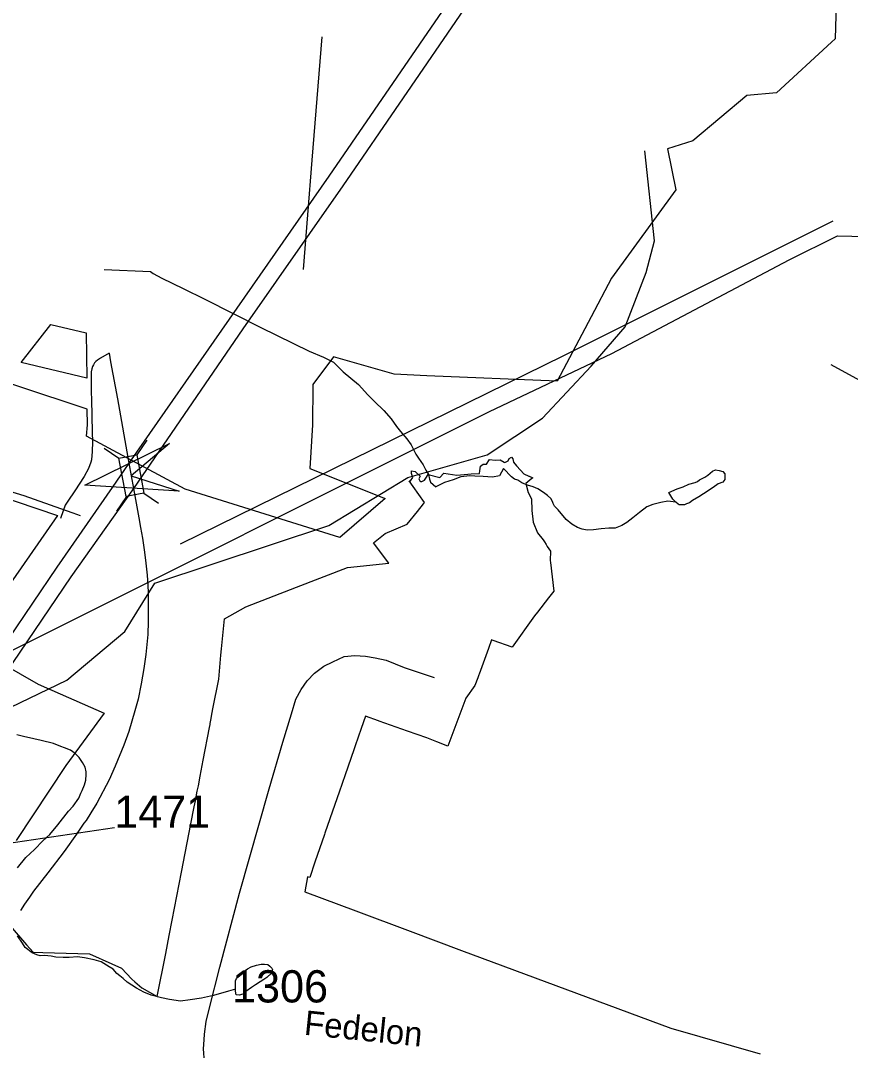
# Model space of a CAD drawing. Extents: x 2260773 to 2342389, y 552869 to 618546.
# Drawn here: x 2298424 to 2301642, y 607573 to 611569 of the extents above; entities that cross this region are included whole.
import ezdxf

# ---------------------------------------------------------------- set-up
doc = ezdxf.new("R2010")
doc.units = 0
for name, color, linetype in [('Exist Boundary Political City Limit New', 7, 'Continuous'), ('Exist Hydrographic Creek Single Shore', 7, 'Continuous'), ('Exist Hydrographic Misc Water Feature', 7, 'Continuous'), ('Exist Road Non-System Type 51', 7, 'Continuous'), ('Exist Road Primary Interstate Divided Center Attributed', 7, 'Continuous'), ('Exist Road Secondary Structure Standard Bridge Attributed CELL', 7, 'Continuous'), ('Exist Road Secondary Structure Standard Bridge CELL', 7, 'Continuous'), ('Exist Road Secondary Type 51 Attributed', 7, 'Continuous'), ('Exist Road Secondary Type 51 Label', 7, 'Continuous'), ('Exist Road Secondary Type 51 Number Label', 7, 'Continuous'), ('Exist Utilities Electrical Transmission Line', 7, 'Continuous'), ('Map Preparation Boundary City Limit Buffer Line', 7, 'Continuous')]:
    doc.layers.add(name, color=color, linetype=linetype)

msp = doc.modelspace()

# ---------------------------------------------------------------- linework, layer by layer
at = {"layer": 'Exist Boundary Political City Limit New'}
for points in [[(2301595.8, 611955.4), (2301583.2, 611498.7), (2301568.8, 611485.4), (2301355, 611288.4), (2301239.8, 611278.1), (2301030.8, 611103.3), (2300932.2, 611071.2), (2300965.2, 610913), (2300715, 610569.1), (2300636.5, 610420), (2300504.5, 610169.6), (2300000, 610191.3), (2299872.8, 610197.1), (2299637, 610264.2), (2299557.5, 610157), (2299557, 610156.4), (2299557, 610153.1), (2299555.8, 610000), (2299545.5, 609830.8), (2299838.2, 609714.4), (2299662.5, 609563.6), (2299062.8, 609750.7), (2298680.2, 609957.1), (2298683.8, 610000)], [(2298542, 610390.1), (2298678, 610357.3), (2298681.5, 610181.9), (2298427, 610242.6), (2298542, 610390.1)], [(2298683.8, 610000), (2298683, 610060.9), (2298635.8, 610076.6), (2297935.5, 610308.8)], [(2298319.2, 608129.9), (2298446.8, 607983.2), (2298473, 607953.8), (2298509.8, 607952.9), (2298691, 607948.4), (2298777.5, 607909.4), (2298815, 607892.5), (2298855.8, 607850), (2298867.5, 607839.4), (2298894, 607815.5), (2298954.2, 607782.6), (2298986.8, 607949.6), (2299000, 608018.4), (2299011.5, 608078.2), (2299048, 608264.7), (2299084.8, 608452.2), (2299097.8, 608518.5), (2299102.2, 608541.6), (2299109.5, 608578.9), (2299113.5, 608599.8), (2299120.5, 608636.8), (2299132.5, 608699.1), (2299156.8, 608825.7), (2299159.2, 608837.9), (2299159.8, 608841.7), (2299162, 608854.1), (2299167, 608883.8), (2299169.5, 608897.9), (2299192.5, 609013.3), (2299201, 609106.6), (2299203.2, 609131.4), (2299214.5, 609247.9), (2299297.5, 609294.4), (2299494.5, 609370.5), (2299691.8, 609446.5), (2299851.8, 609463.5), (2299793.2, 609542.6), (2299838, 609578.6), (2299923, 609615.1), (2299963.2, 609664.7), (2299987, 609694.1), (2299990.8, 609698.7), (2299946, 609761.8), (2299930.8, 609783), (2299936.5, 609783.9), (2299945, 609796.4), (2299939.5, 609811.6), (2299939.5, 609821.7), (2299954.8, 609819), (2299973.2, 609802), (2299968.2, 609790.6), (2299971.8, 609782.8), (2299976.2, 609781.3), (2299979.5, 609780.2), (2299990.5, 609785.6), (2299995.2, 609793.1), (2300005, 609808.2), (2300049.8, 609796.4), (2300065.8, 609812.8), (2300115.5, 609804.7), (2300158.5, 609809.4), (2300171.2, 609809.9), (2300203.5, 609811.2), (2300205, 609822.1), (2300207.2, 609840), (2300218, 609848.2), (2300230.5, 609847.6), (2300242.8, 609866.1), (2300264.2, 609863.6), (2300284.2, 609864.7), (2300300, 609856.2), (2300302.5, 609854.9), (2300314.5, 609861.4), (2300318.2, 609870.2), (2300327.2, 609874.7), (2300332.8, 609868.6), (2300335.8, 609856.2), (2300347.8, 609841.1), (2300348.5, 609840.2)], [(2300348.5, 609840.2), (2300375.8, 609810.8), (2300395, 609802), (2300395.8, 609801.6), (2300410.2, 609795.2), (2300407, 609792.4), (2300383.5, 609773.2), (2300392.2, 609738.4), (2300405, 609712.9), (2300406.5, 609668.4), (2300411.5, 609622.7), (2300428.8, 609581.6), (2300450.2, 609553.7), (2300455.8, 609546.5), (2300462, 609535.8), (2300466.5, 609528.8), (2300479, 609510), (2300478, 609473.5), (2300479, 609466.6), (2300491.5, 609354.9), (2300471.2, 609329.1), (2300428, 609273.9), (2300416.5, 609259.2), (2300330.2, 609138.2), (2300257.2, 609164.2), (2300250.5, 609166.7), (2300238, 609132.6), (2300201.8, 609033.1), (2300200.8, 609030.2), (2300196.8, 609019.1), (2300185.8, 608988.9), (2300150.8, 608939.6), (2300093.2, 608785.1), (2300081.5, 608753.8), (2300038.2, 608770.5), (2300000, 608785.4), (2299924.2, 608812.3), (2299814.5, 608851.2), (2299811.8, 608852.2), (2299761.8, 608869.9), (2299745.2, 608822.2), (2299722.2, 608755.4), (2299716.8, 608739.6), (2299683, 608642.1), (2299659.8, 608575.2), (2299643.2, 608527.7), (2299604.5, 608415.8), (2299602.8, 608410.7), (2299565.8, 608303.5), (2299545.2, 608244.4), (2299536.8, 608246.7), (2299525.8, 608188), (2299724.2, 608114.2), (2299934.8, 608036.1), (2300134.2, 607960.1), (2300945.8, 607659.8), (2301291.8, 607559.1)], [(2298325.2, 609730.6), (2298567, 609649.4), (2298328.2, 609305.6)], [(2298220.8, 609150), (2298492, 608994.4), (2298747.8, 608881.1), (2298599.5, 608678.1), (2298407, 608388.1)]]:
    msp.add_lwpolyline(points, dxfattribs=at)
at = {"layer": 'Exist Hydrographic Creek Single Shore'}
msp.add_lwpolyline([(2298012.3, 608776.9), (2298210.8, 608879.9), (2298386.5, 608905), (2298603.8, 609010.2), (2298828.3, 609199), (2298945.2, 609385.7)], dxfattribs=at)
at = {"layer": 'Exist Hydrographic Misc Water Feature'}
for points in [[(2299521.5, 610603.9), (2299554.9, 611027.9), (2299593.9, 611506.3)], [(2298945.2, 609385.7), (2299618.9, 609609.6), (2299925.9, 609795.9), (2300232.9, 609883.8), (2300447.9, 610027), (2300637, 610228.3), (2300769.1, 610381.3), (2300850.1, 610591.3), (2300882, 610714.1), (2300844.9, 611063.6)], [(2298747.9, 610603.6), (2298928.1, 610595.6), (2298937.7, 610587.6), (2298972.2, 610570.3), (2299054.2, 610529.1), (2299138.7, 610488), (2299356, 610378.2), (2299543.1, 610286.4), (2299599, 610263), (2299637, 610243.5), (2299675.7, 610206), (2299734.4, 610156.6), (2299770.7, 610116.7), (2299796.5, 610091.3), (2299833.2, 610055.8), (2299861.5, 610024), (2299881.6, 609994.1), (2299897.8, 609974.3), (2299922, 609946.6), (2299938.4, 609922.7), (2299956.9, 609887.1), (2299966.9, 609871), (2299985.1, 609845.5), (2299995.4, 609825.3), (2300005.7, 609807.6), (2300010, 609789.9), (2300013.9, 609777.9), (2300034.2, 609759.8)], [(2300297.2, 609830.9), (2300281.4, 609802.5), (2300254, 609798.1), (2300217.7, 609799.9), (2300185.7, 609801.5), (2300166, 609803.3), (2300131.8, 609799.1), (2300102, 609786.6), (2300068, 609776.2), (2300040.1, 609762.2), (2300034.2, 609759.8)], [(2300964.5, 609700.1), (2300933.9, 609703.9), (2300906.4, 609699.5), (2300876.5, 609691), (2300852.7, 609682.8), (2300824.8, 609660.7), (2300798.8, 609640.2), (2300775, 609621.9), (2300755.5, 609609.8), (2300729.7, 609599.6), (2300705.3, 609599.2), (2300675.8, 609597.1), (2300645.6, 609592.8), (2300621.8, 609592.3), (2300601.5, 609596.2), (2300583.9, 609602.1), (2300561.3, 609615.6), (2300539.4, 609633.5), (2300509.1, 609670.9), (2300494.7, 609684.8), (2300488.8, 609695), (2300486.7, 609702.7), (2300480.6, 609714.9), (2300468, 609726.6), (2300452.3, 609738.3), (2300429.9, 609752.2), (2300411.7, 609760.2), (2300390.1, 609765.9), (2300368, 609775.7), (2300351.8, 609785.5), (2300339.7, 609789.3), (2300327.6, 609799.2), (2300297.2, 609830.9)], [(2300964.5, 609700.1), (2300954, 609711.8), (2300938, 609737.7), (2300969.6, 609752), (2300994, 609760.1), (2301015.7, 609770.6), (2301039.5, 609776.8), (2301049.2, 609781), (2301057.2, 609787.1), (2301077.5, 609797), (2301088.9, 609805.4), (2301107, 609821.4), (2301118.7, 609825.7), (2301132.8, 609823.6), (2301147.2, 609819.8), (2301154.8, 609810.1), (2301155, 609795.9), (2301155, 609788.2), (2301147.4, 609778), (2301129.7, 609771.7), (2301109.7, 609757.7), (2301071.9, 609733), (2301053.7, 609721.1), (2301030.1, 609706.8), (2301018.2, 609698.5), (2301006.3, 609694.6), (2300998.5, 609690.5), (2300978.4, 609690.3), (2300974.5, 609692.1), (2300964.5, 609700.1)], [(2298412.8, 608281.3), (2298444.2, 608321.6), (2298478.2, 608352.2), (2298510.2, 608386.3), (2298537.7, 608410.5), (2298569.1, 608448.8), (2298610.5, 608501.3), (2298627.9, 608521.4), (2298649.8, 608551.8), (2298657.4, 608571.7), (2298663.4, 608581.8), (2298671.4, 608604.1), (2298676.9, 608621.9), (2298679, 608644), (2298678.8, 608654), (2298674.7, 608671.7), (2298664.4, 608689.9), (2298651.9, 608709.6), (2298635.9, 608725.4), (2298617.9, 608737.5), (2298594.1, 608747.1), (2298580.1, 608752.9), (2298551.4, 608764.5), (2298503.6, 608776.2), (2298475.8, 608781.6), (2298435.2, 608791.3), (2298409.5, 608797.2)], [(2299257.6, 607810.6), (2299229.9, 607802.6), (2299171.9, 607785.8), (2299126, 607775.2), (2299081.9, 607768.9), (2299044.2, 607764.4), (2299002.1, 607770), (2298970.3, 607777.6), (2298929.9, 607787.3), (2298902.1, 607798.8), (2298873.6, 607814.5), (2298855.7, 607826.5), (2298837.7, 607838.1), (2298821.7, 607851.9), (2298809.2, 607861.9), (2298797.3, 607871.8), (2298782.9, 607887.8), (2298767.1, 607897.4), (2298736.4, 607917), (2298708.9, 607924.9), (2298672.6, 607932.3), (2298644.7, 607936.1), (2298612.5, 607933.7), (2298588.7, 607933.6), (2298560.4, 607935), (2298542.4, 607939), (2298516.8, 607940.8), (2298500.6, 607940.4), (2298486.8, 607944.5), (2298468.6, 607952.1), (2298442.5, 607971.8), (2298431.9, 607989.7), (2298411.8, 608017.5)], [(2299257.6, 607810.6), (2299257.2, 607818.8), (2299257.4, 607832.5), (2299257.4, 607842.7), (2299261.1, 607852.6), (2299271, 607862.9), (2299281.2, 607872.7), (2299304.6, 607889.1), (2299318.7, 607897.5), (2299338.4, 607903.5), (2299356.7, 607907.6), (2299370.2, 607908), (2299382.3, 607906.2), (2299390.7, 607900.1), (2299398.7, 607892.3), (2299400.7, 607886.4), (2299397.1, 607872.3), (2299379, 607856), (2299367.1, 607848), (2299353, 607839.6), (2299335.7, 607827.6), (2299319.5, 607817.5), (2299297.6, 607801.3), (2299285.7, 607790.9), (2299272, 607786.9), (2299259.9, 607788.7), (2299257.6, 607802.9), (2299257.6, 607810.6)]]:
    msp.add_lwpolyline(points, dxfattribs=at)
at = {"layer": 'Exist Road Non-System Type 51'}
for p, q in [((2298627.5, 609657.9), (2298580.5, 609674.6)), ((2298656.3, 609647.6), (2298627.5, 609657.9))]:
    msp.add_line(p, q, dxfattribs=at)
for points in [[(2302669.5, 609785.8), (2302626.9, 609800), (2302263.5, 609920.8), (2301997.8, 610015.3), (2301874.8, 610070.3), (2301782.6, 610123), (2301664, 610180.1), (2301567.3, 610232.9)], [(2298580.5, 609674.6), (2298438.2, 609725.3), (2298348.8, 609751.6), (2298326.9, 609773.6), (2298279.4, 609821.1)], [(2299136.1, 607614), (2299137.4, 607635.5), (2299144, 607684.9), (2299157.2, 607737.7), (2299196.7, 607895.9), (2299272.5, 608182.7), (2299387.8, 608588.1), (2299440.5, 608769.4), (2299474.5, 608879.2), (2299492.1, 608936.4), (2299511.8, 608973.7), (2299536, 609006.7), (2299564.5, 609037.5), (2299599.7, 609063.8), (2299634.8, 609081.4), (2299678.7, 609101.2), (2299720.5, 609105.6), (2299762.2, 609103.4), (2299799.5, 609096.8), (2299841.2, 609088), (2299911.5, 609059.4), (2300027.9, 609019.9)], [(2299137.4, 607527.2), (2299134.1, 607579.5), (2299136.1, 607614)]]:
    msp.add_lwpolyline(points, dxfattribs=at)
at = {"layer": 'Exist Road Primary Interstate Divided Center Attributed'}
for points in [[(2301053.9, 613030.6), (2300322.2, 611991.3), (2299619.5, 610965.1), (2299232.7, 610410.4), (2298844.5, 609852.1)], [(2301111.8, 612998.5), (2300376.1, 611953.9), (2299673.5, 610927.8), (2299286.6, 610372.9), (2298862.1, 609753.4)], [(2298844.5, 609852.1), (2298779.6, 609757.5), (2298564.9, 609447.7), (2298280.6, 609029.8), (2298078.5, 608714.6), (2297910.7, 608420), (2297811.4, 608214.4), (2297736.1, 608043.2), (2297575.1, 607625.2), (2297438.1, 607145.6), (2297328.5, 606669.4), (2297208.7, 606052.8), (2297112.8, 605669.1), (2297040.9, 605439.5), (2296893.6, 605018.2), (2296605.9, 604305.6), (2296386.7, 603730), (2296248.2, 603378.4), (2296202.7, 603264.5), (2296044.3, 602853), (2295787.4, 602202.1), (2295553.8, 601595.1)], [(2298862.1, 609753.4), (2298618.9, 609410.6), (2298335.4, 608993.6), (2298134.7, 608680.6), (2297968.8, 608389.4), (2297871, 608186.9), (2297796.7, 608018.1), (2297637.4, 607604.4), (2297501.7, 607129.2), (2297392.7, 606655.8), (2297272.7, 606038.5), (2297176, 605651.3), (2297103.1, 605418.9), (2296955, 604995), (2296667, 604281.6), (2296448.1, 603706.8), (2296328.1, 603387.7), (2296105.3, 602828.8), (2295848.5, 602178.3), (2295615.8, 601573.6)]]:
    msp.add_lwpolyline(points, dxfattribs=at)
at = {"layer": 'Exist Road Secondary Structure Standard Bridge Attributed CELL'}
msp.add_lwpolyline([(2299038.9, 609742.7), (2298673.9, 609766.6), (2299002, 609928.4), (2298853.3, 609802.3)], close=True, dxfattribs=at)
at = {"layer": 'Exist Road Secondary Structure Standard Bridge CELL'}
for p, q in [((2298748.3, 609909.9), (2298805.3, 609871)), ((2298913.6, 609941), (2298874.6, 609884)), ((2298834.5, 609722.7), (2298795.6, 609665.7)), ((2298902.3, 609735.5), (2298959.2, 609696.6))]:
    msp.add_line(p, q, dxfattribs=at)
msp.add_lwpolyline([(2298874.6, 609884), (2298902.6, 609735.5), (2298833.2, 609722.5), (2298805.3, 609871)], close=True, dxfattribs=at)
at = {"layer": 'Exist Road Secondary Type 51 Attributed'}
for points in [[(2298767.3, 610278.4), (2298733.7, 610259.1), (2298722.6, 610252.1), (2298716.3, 610246.7), (2298711.2, 610241), (2298706.8, 610234), (2298703.3, 610226.7), (2298700.1, 610218.5), (2298697.9, 610206.1), (2298698.2, 610127.6), (2298699.8, 610098.7), (2298702.3, 609971.7), (2298702.9, 609935.2), (2298701.7, 609896.8), (2298699.1, 609864.7), (2298696.9, 609856.1), (2298687.1, 609831.3), (2298670.9, 609799.6), (2298634.7, 609745), (2298607, 609704.6), (2298597.2, 609689.4), (2298589.9, 609667.5), (2298578.8, 609637.3)], [(2298767.3, 610278.4), (2298773.3, 610245.4), (2298800.1, 610101.6), (2298844.5, 609852.1)], [(2298844.5, 609852.1), (2298862.1, 609753.4)], [(2298862.1, 609753.4), (2298882.7, 609639.8), (2298888.7, 609601.7), (2298896.7, 609561.1), (2298903.7, 609516), (2298908.7, 609475), (2298914.8, 609417.5), (2298917.9, 609379.1), (2298919.5, 609347.4), (2298919.5, 609323.5), (2298919.5, 609274.6), (2298919.5, 609237.8), (2298917, 609186.7), (2298909.7, 609108.9), (2298902.7, 609055.5), (2298892.2, 608995.2), (2298879.5, 608936.1), (2298867.1, 608890.4), (2298843.6, 608811), (2298825, 608757.9), (2298791.5, 608675.4), (2298767.4, 608622.7), (2298720.1, 608533.1), (2298696.3, 608494.7), (2298677.9, 608465.5), (2298669.8, 608455.1), (2298641.3, 608412.7), (2298593.1, 608344.8), (2298529.2, 608262.2), (2298474, 608190.7), (2298458.4, 608168.2), (2298439, 608140.3), (2298423.2, 608116.1)]]:
    msp.add_lwpolyline(points, dxfattribs=at)
at = {"layer": 'Exist Road Secondary Type 51 Number Label'}
msp.add_line((2298243.8, 608356.8), (2298788.5, 608438.5), dxfattribs=at)
at = {"layer": 'Exist Utilities Electrical Transmission Line'}
for points in [[(2301573.6, 610790.5), (2300530, 610268.7), (2299042.7, 609536.9)], [(2298340.3, 609100.8), (2300242.1, 610052.4), (2300717.2, 610277.6), (2301404.8, 610640.4), (2301592.4, 610734.2), (2302646.6, 610709.4)]]:
    msp.add_lwpolyline(points, dxfattribs=at)
at = {"layer": 'Map Preparation Boundary City Limit Buffer Line'}
for points in [[(2301595.8, 611955.4), (2301583.2, 611498.7), (2301568.8, 611485.4), (2301355, 611288.4), (2301239.8, 611278.1), (2301030.8, 611103.3), (2300932.2, 611071.2), (2300965.2, 610913), (2300715, 610569.1), (2300636.5, 610420), (2300504.5, 610169.6), (2300000, 610191.3), (2299872.8, 610197.1), (2299637, 610264.2), (2299557.5, 610157), (2299557, 610156.4), (2299557, 610153.1), (2299555.8, 610000), (2299545.5, 609830.8), (2299838.2, 609714.4), (2299662.5, 609563.6), (2299062.8, 609750.7), (2298680.2, 609957.1), (2298683.8, 610000)], [(2298542, 610390.1), (2298678, 610357.3), (2298681.5, 610181.9), (2298427, 610242.6), (2298542, 610390.1)], [(2298683.8, 610000), (2298683, 610060.9), (2298635.8, 610076.6), (2297935.5, 610308.8)], [(2298319.2, 608129.9), (2298446.8, 607983.2), (2298473, 607953.8), (2298509.8, 607952.9), (2298691, 607948.4), (2298777.5, 607909.4), (2298815, 607892.5), (2298855.8, 607850), (2298867.5, 607839.4), (2298894, 607815.5), (2298954.2, 607782.6), (2298986.8, 607949.6), (2299000, 608018.4), (2299011.5, 608078.2), (2299048, 608264.7), (2299084.8, 608452.2), (2299097.8, 608518.5), (2299102.2, 608541.6), (2299109.5, 608578.9), (2299113.5, 608599.8), (2299120.5, 608636.8), (2299132.5, 608699.1), (2299156.8, 608825.7), (2299159.2, 608837.9), (2299159.8, 608841.7), (2299162, 608854.1), (2299167, 608883.8), (2299169.5, 608897.9), (2299192.5, 609013.3), (2299201, 609106.6), (2299203.2, 609131.4), (2299214.5, 609247.9), (2299297.5, 609294.4), (2299494.5, 609370.5), (2299691.8, 609446.5), (2299851.8, 609463.5), (2299793.2, 609542.6), (2299838, 609578.6), (2299923, 609615.1), (2299963.2, 609664.7), (2299987, 609694.1), (2299990.8, 609698.7), (2299946, 609761.8), (2299930.8, 609783), (2299936.5, 609783.9), (2299945, 609796.4), (2299939.5, 609811.6), (2299939.5, 609821.7), (2299954.8, 609819), (2299973.2, 609802), (2299968.2, 609790.6), (2299971.8, 609782.8), (2299976.2, 609781.3), (2299979.5, 609780.2), (2299990.5, 609785.6), (2299995.2, 609793.1), (2300005, 609808.2), (2300049.8, 609796.4), (2300065.8, 609812.8), (2300115.5, 609804.7), (2300158.5, 609809.4), (2300171.2, 609809.9), (2300203.5, 609811.2), (2300205, 609822.1), (2300207.2, 609840), (2300218, 609848.2), (2300230.5, 609847.6), (2300242.8, 609866.1), (2300264.2, 609863.6), (2300284.2, 609864.7), (2300300, 609856.2), (2300302.5, 609854.9), (2300314.5, 609861.4), (2300318.2, 609870.2), (2300327.2, 609874.7), (2300332.8, 609868.6), (2300335.8, 609856.2), (2300347.8, 609841.1), (2300348.5, 609840.2)], [(2300348.5, 609840.2), (2300375.8, 609810.8), (2300395, 609802), (2300395.8, 609801.6), (2300410.2, 609795.2), (2300407, 609792.4), (2300383.5, 609773.2), (2300392.2, 609738.4), (2300405, 609712.9), (2300406.5, 609668.4), (2300411.5, 609622.7), (2300428.8, 609581.6), (2300450.2, 609553.7), (2300455.8, 609546.5), (2300462, 609535.8), (2300466.5, 609528.8), (2300479, 609510), (2300478, 609473.5), (2300479, 609466.6), (2300491.5, 609354.9), (2300471.2, 609329.1), (2300428, 609273.9), (2300416.5, 609259.2), (2300330.2, 609138.2), (2300257.2, 609164.2), (2300250.5, 609166.7), (2300238, 609132.6), (2300201.8, 609033.1), (2300200.8, 609030.2), (2300196.8, 609019.1), (2300185.8, 608988.9), (2300150.8, 608939.6), (2300093.2, 608785.1), (2300081.5, 608753.8), (2300038.2, 608770.5), (2300000, 608785.4), (2299924.2, 608812.3), (2299814.5, 608851.2), (2299811.8, 608852.2), (2299761.8, 608869.9), (2299745.2, 608822.2), (2299722.2, 608755.4), (2299716.8, 608739.6), (2299683, 608642.1), (2299659.8, 608575.2), (2299643.2, 608527.7), (2299604.5, 608415.8), (2299602.8, 608410.7), (2299565.8, 608303.5), (2299545.2, 608244.4), (2299536.8, 608246.7), (2299525.8, 608188), (2299724.2, 608114.2), (2299934.8, 608036.1), (2300134.2, 607960.1), (2300945.8, 607659.8), (2301291.8, 607559.1)], [(2298325.2, 609730.6), (2298567, 609649.4), (2298328.2, 609305.6)], [(2298220.8, 609150), (2298492, 608994.4), (2298747.8, 608881.1), (2298599.5, 608678.1), (2298407, 608388.1)]]:
    msp.add_lwpolyline(points, dxfattribs=at)

# ---------------------------------------------------------------- texts
at = {"layer": 'Exist Road Secondary Type 51 Label'}
msp.add_text('Fedelon', height=95, rotation=354.1468, dxfattribs=at).set_placement((2299520.8, 607634.1))
at = {"layer": 'Exist Road Secondary Type 51 Number Label'}
for s, p in [('1471', (2298787.5, 608436.9)), ('1306', (2299244.4, 607759.1))]:
    msp.add_text(s, height=125, dxfattribs=at).set_placement(p)

doc.saveas('drawing.dxf')
